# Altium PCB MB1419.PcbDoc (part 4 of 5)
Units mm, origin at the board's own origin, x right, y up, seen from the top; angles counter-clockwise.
Board outline 31 x 41 mm, 8 copper layers (Top Layer, Signal Layer 1, Signal Layer 2, Signal Layer 3, Signal Layer 4, Signal Layer 5, Signal Layer 6, Bottom Layer), stack 1.536 mm thick; 212 components, 125 nets, 637 pads, 2405 vias.
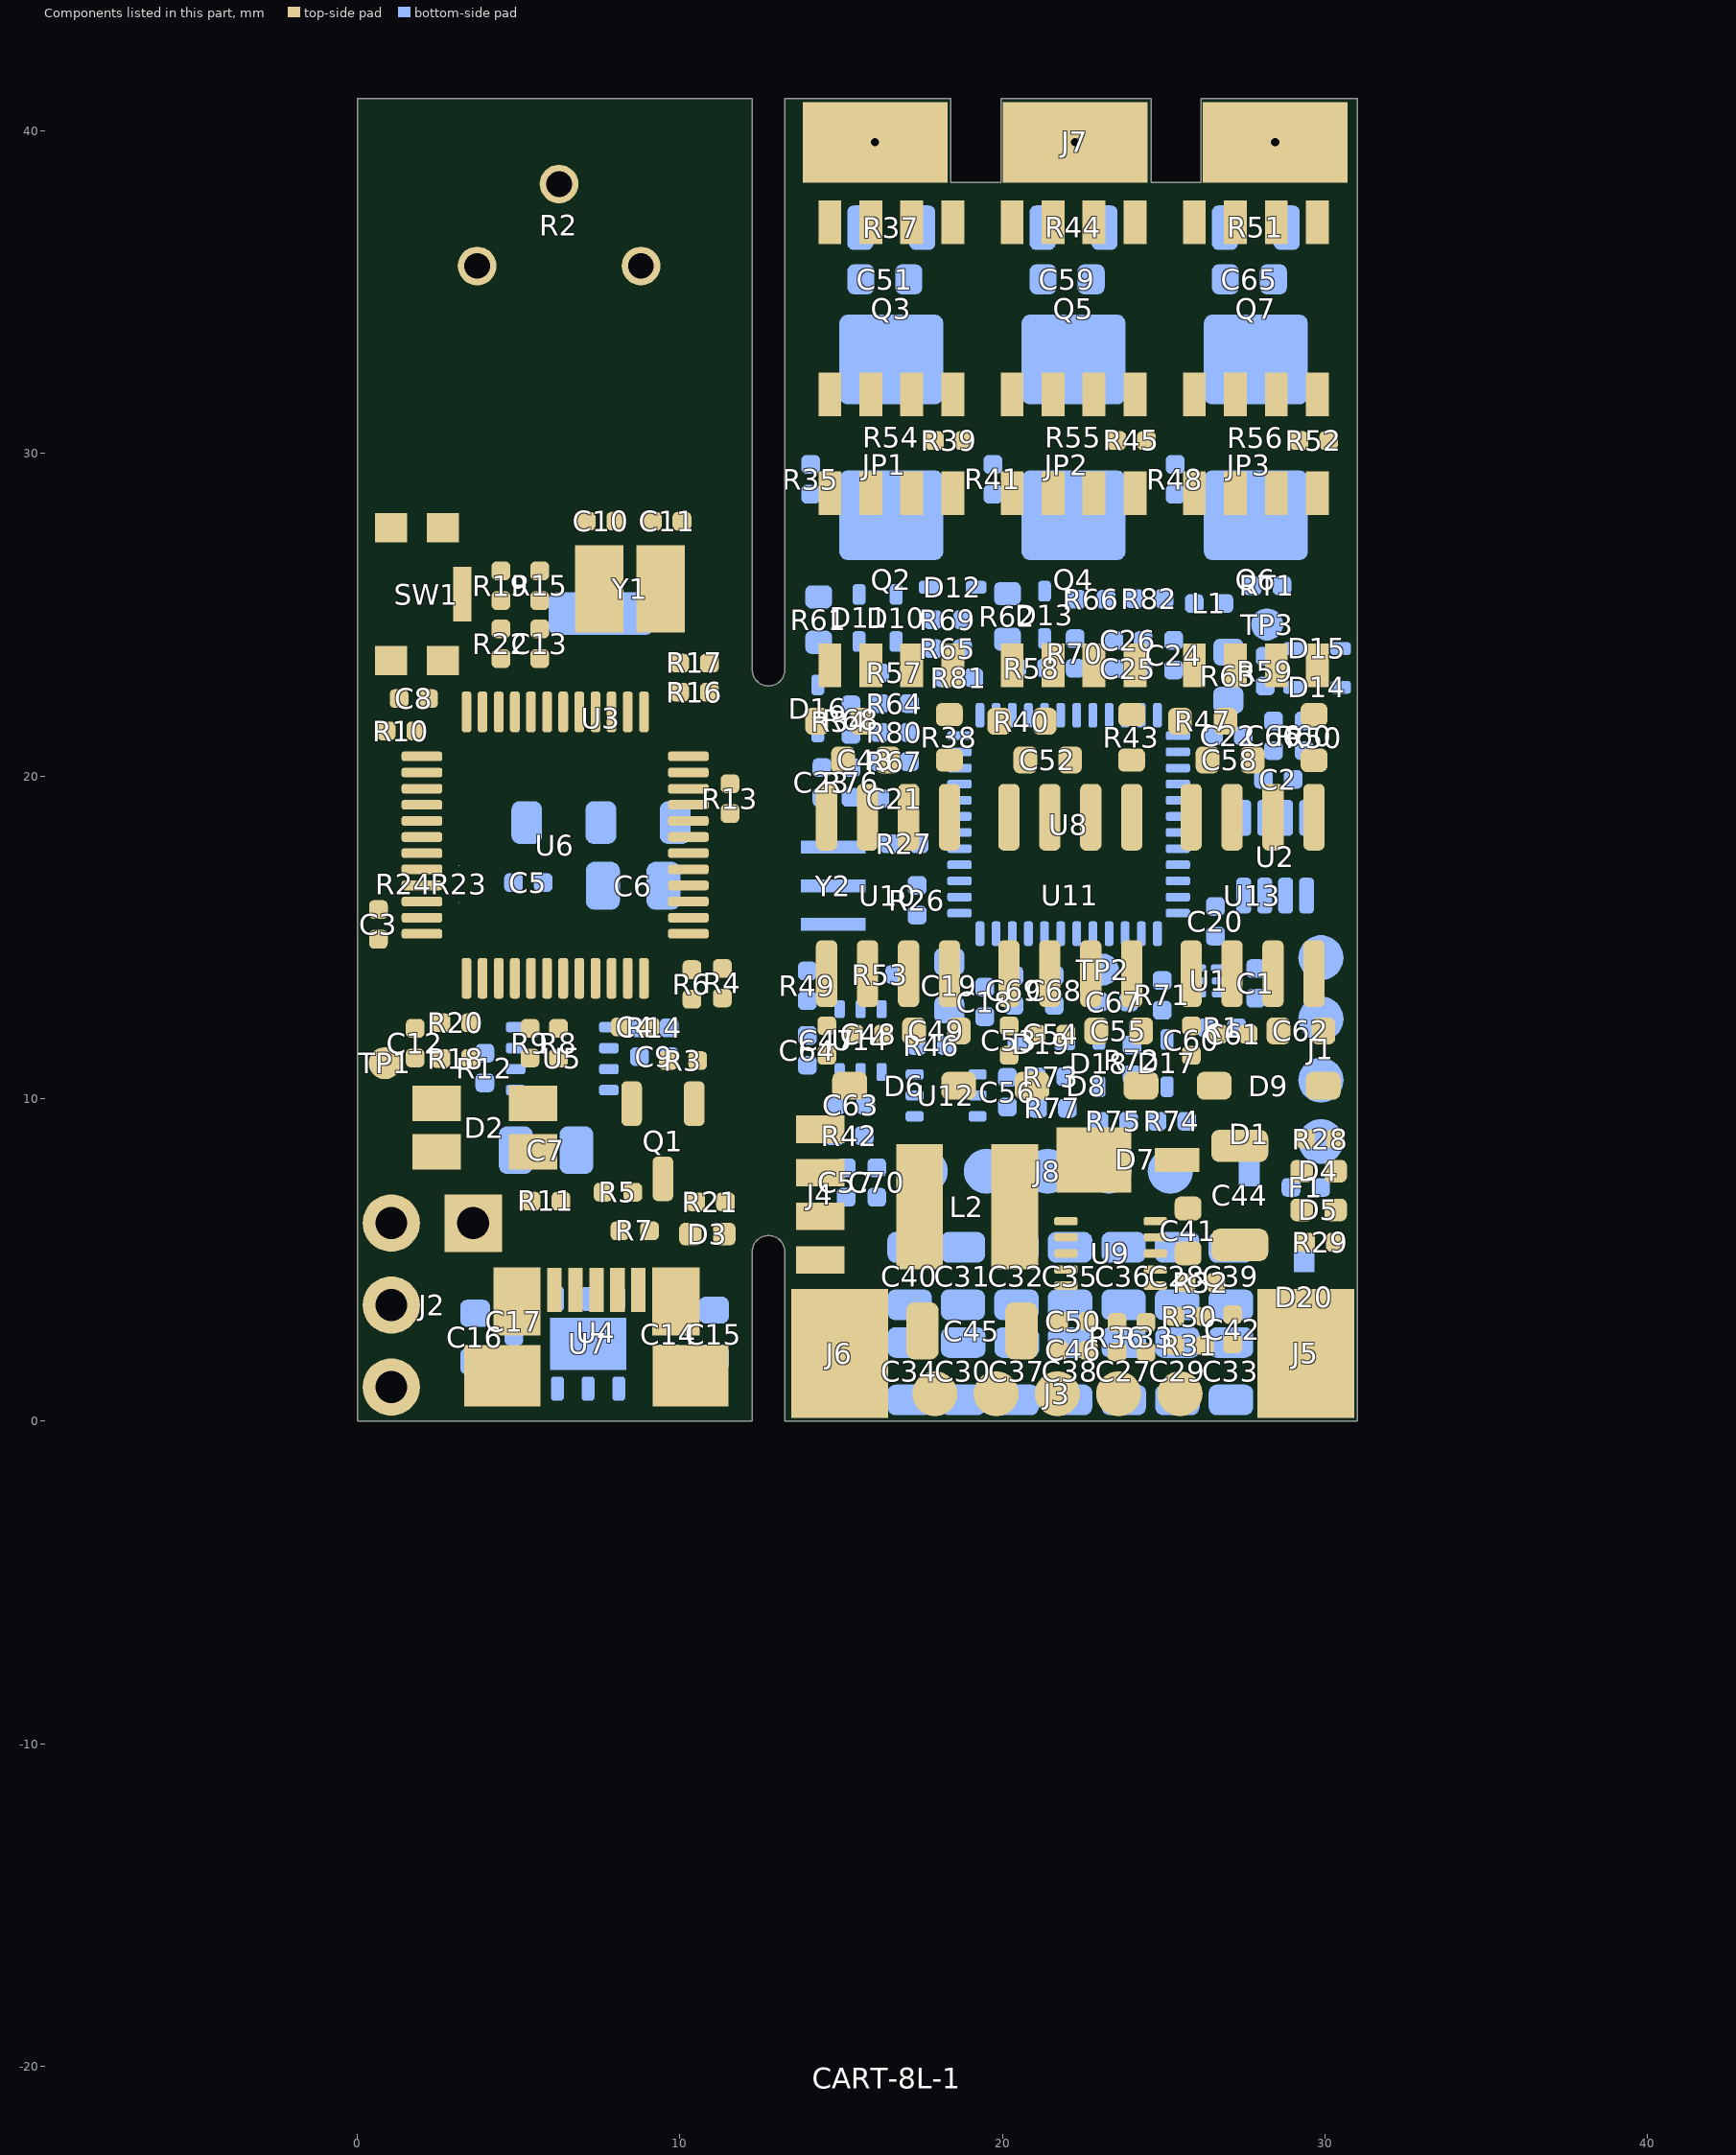
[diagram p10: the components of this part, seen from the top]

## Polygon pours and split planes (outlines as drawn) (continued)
V+ on Bottom Layer "V+_L08_P048" (solid, pour order 48): 27.65,2 16.65,2 16.65,4 27.65,4 30.75,4 30.85,3.9 30.85,0.1 28.05,0.1 28.05,1.6 27.65,2
"VSHUNT_2 +" on Bottom Layer "VSHUNT_2_+_L08_P050" (solid, pour order 50): 19.8,34.4 19.8,30.8 20.4,30.2 23.4,30.2 23.8,30.6 23.8,34.2 23.4,34.6 20,34.6 19.8,34.4
"VSHUNT_3 +" on Bottom Layer "VSHUNT_3_+_L08_P052" (solid, pour order 52): 25.45,34.4 25.45,30.8 26.05,30.2 29.05,30.2 29.45,30.6 29.45,34.2 29.05,34.6 25.65,34.6 25.45,34.4
"VSHUNT_1 +" on Bottom Layer "VSHUNT_1_+_L08_P054" (solid, pour order 54): 14.15,34.4 14.15,30.8 14.75,30.2 17.75,30.2 18.15,30.6 18.15,34.2 17.75,34.6 14.35,34.6 14.15,34.4
D on Bottom Layer "D_L08_P056" (solid, pour order 56): 42 vertices, not listed, extent 29.25,9.9 30.725,11.25
OUT3 on Bottom Layer "OUT3_L08_P058" (solid, pour order 58): 26.2,40.9 26.2,38 30.7,38 30.7,40.9 26.2,40.9
OUT1 on Bottom Layer "OUT1_L08_P060" (solid, pour order 60): 13.8,40.9 13.8,38 18.3,38 18.3,40.9 13.8,40.9
OUT2 on Bottom Layer "OUT2_L08_P062" (solid, pour order 62): 20,40.9 20,38 24.5,38 24.5,40.9 20,40.9
NetF1_1 on Bottom Layer "NETF1_1_L08_P064" (solid, pour order 64): 42 vertices, not listed, extent 29.225,7.95 30.725,9.35
+10V on Bottom Layer "+10V_L08_P066" (solid, pour order 66): 11.9,9.25 12.25,9.25 12.3,9.3 12.3,9.95 11.95,10.3 11.55,10.3 11.5,10.25 11.5,9.65 11.9,9.25
+10V on Bottom Layer "+10V_L08_P068" (solid, pour order 68): 13.25,9.3 14.15,9.3 14.2,9.35 14.2,10.45 14.15,10.5 13.75,10.5 13.25,10 13.25,9.3
+10V on Bottom Layer "+10V_L08_P070" (solid, pour order 70): 19,10.25 19,9.1 19.1,9 20.4,9 20.5,9.1 20.5,10 20.4,10.1 19.85,10.1 19.7,10.25 19,10.25
+5V on Bottom Layer "+5V_L08_P072" (solid, pour order 72): 11.5,9.05 12.25,9.05 12.3,9 12.3,8.45 12.25,8.4 11.55,8.4 11.45,8.5 11.45,9 11.5,9.05
+5V on Bottom Layer "+5V_L08_P074" (solid, pour order 74): 13.3,7.7 14.05,7.7 14.2,7.85 14.2,8.75 14,8.95 13.3,8.95 13.2,8.85 13.2,7.8 13.3,7.7
USART2_RX on Top Layer "USART2_RX_L01_P076" (solid, pour order 76): 42 vertices, not listed, extent 21,0.075 22.4,1.575
USART2_RX_ST_LINK on Top Layer "USART2_RX_ST_LINK_L01_P078" (solid, pour order 78): 42 vertices, not listed, extent 19.1,0.075 20.5,1.575
+3.3V on Top Layer "+3.3V_L01_P080" (solid, pour order 80): 13.4,6.75 13.4,5.95 15.55,5.95 15.55,6.75 13.4,6.75
GND on Top Layer "GND_L01_P082" (solid, pour order 82): 24.75,7.8 24.75,8.8 24.95,9 28.05,9 28.15,8.9 28.15,7.9 27.85,7.6 24.95,7.6 24.75,7.8
GND on Top Layer "GND_L01_P084" (solid, pour order 84): 42 vertices, not listed, extent 24.8,0.075 26.2,1.575
GND on Top Layer "GND_L01_P086" (solid, pour order 86): 21.1,3.55 21.1,2.1 21,2 19.85,2 19.75,2.1 19.75,3.5 19.85,3.6 21.05,3.6 21.1,3.55
GND on Top Layer "GND_L01_P088" (solid, pour order 88): 13.375,5.4 13.375,4.6 15.525,4.6 15.525,5.4 13.375,5.4
GND on Top Layer "GND_L01_P090" (solid, pour order 90): 13.35,5.3 13.35,0.1 16.45,0.1 16.45,4.2 15.25,5.4 13.45,5.4 13.35,5.3
NetD7_C on Top Layer "NETD7_C_L01_P092" (solid, pour order 92): 23.95,9.1 21.75,9.1 21.25,8.6 19.65,8.6 19.65,5.6 22.25,5.6 22.25,6.9 22.35,7 23.95,7 23.95,9.1
V+ on Top Layer "V+_L01_P094" (solid, pour order 94): 19 vertices, not listed, extent 24.45,0.1 30.85,7
V+ on Top Layer "V+_L01_P096" (solid, pour order 96): 19.3,27.3 19.3,22.7 25,22.7 25,27.3 19.3,27.3
V+ on Top Layer "V+_L01_P098" (solid, pour order 98): 24.95,27.3 24.95,22.7 30.65,22.7 30.65,27.3 24.95,27.3
V+ on Top Layer "V+_L01_P100" (solid, pour order 100): 13.65,27.3 13.65,22.7 19.35,22.7 19.35,27.3 13.65,27.3
"VSHUNT_2 +" on Top Layer "VSHUNT_2_+_L01_P102" (solid, pour order 102): 19.8,32.8 19.8,30.8 20.3,30.3 23.2,30.3 23.2,32.8 19.8,32.8
T_JTMS on Top Layer "T_JTMS_L01_P104" (solid, pour order 104): 13.4,9.45 13.4,8.65 15.55,8.65 15.55,9.45 13.4,9.45
T_JTCK on Top Layer "T_JTCK_L01_P106" (solid, pour order 106): 13.4,8.1 13.4,7.3 15.55,7.3 15.55,8.1 13.4,8.1
"VSHUNT_3 +" on Top Layer "VSHUNT_3_+_L01_P108" (solid, pour order 108): 25.45,32.8 25.45,30.8 25.95,30.3 28.85,30.3 28.85,32.8 25.45,32.8
"VSHUNT_1 +" on Top Layer "VSHUNT_1_+_L01_P110" (solid, pour order 110): 14.15,32.8 14.15,30.8 14.65,30.3 17.55,30.3 17.55,32.8 14.15,32.8
OUT3 on Top Layer "OUT3_L01_P112" (solid, pour order 112): 25.1,38.25 25.1,33.3 30.75,33.3 30.75,40.9 26.25,40.9 26.25,38.25 25.1,38.25
OUT3 on Top Layer "OUT3_L01_P114" (solid, pour order 114): 26.8,27.9 26.8,29.8 30.15,29.8 30.15,27.9 26.8,27.9
OUT1 on Top Layer "OUT1_L01_P116" (solid, pour order 116): 13.55,40.9 13.55,33.3 19.15,33.3 19.15,38.2 18.25,38.2 18.25,40.9 13.55,40.9
OUT1 on Top Layer "OUT1_L01_P118" (solid, pour order 118): 15.5,27.9 15.5,29.8 18.85,29.8 18.85,27.9 15.5,27.9
OUT2 on Top Layer "OUT2_L01_P120" (solid, pour order 120): 19.5,38.15 19.5,33.3 24.8,33.3 24.8,38.25 24.45,38.25 24.45,38.45 24.45,40.9 20.05,40.9 20.05,38.25 20.05,38.15 19.5,38.15
OUT2 on Top Layer "OUT2_L01_P122" (solid, pour order 122): 21.15,27.9 21.15,29.8 24.5,29.8 24.5,27.9 21.15,27.9
PWM on Top Layer "PWM_L01_P124" (solid, pour order 124): 42 vertices, not listed, extent 22.9,0.075 24.3,1.575
+10V on Top Layer "+10V_L01_P126" (solid, pour order 126): 30 vertices, not listed, extent 16.65,2 30.45,10.7
+5V on Top Layer "+5V_L01_P128" (solid, pour order 128): 42 vertices, not listed, extent 17.2,0.1 18.6,1.6
+3V3_ST_LINK on Signal Layer 5 "+3V3_ST_LINK_L06_P130" (solid, pour order 130): 988 vertices, not listed, extent 0.25,0.2 12.05,40.7
GND on Signal Layer 5 "GND_L06_P134" (solid, pour order 134): 25.7,29.5 30.75,29.5 30.75,26.5 13.45,26.5 13.45,28.1 14.4,28.1 14.4,29.5 18.95,29.5 18.95,28.1 20.05,28.1 20.05,29.5 24.6,29.5 24.6,28.1 25.7,28.1 25.7,29.5
GND on Signal Layer 5 "GND_L06_P136" (solid, pour order 136): 19.55,2.05 21.6,2.05 21.7,2.15 21.7,3.7 21.6,3.8 19.55,3.8 19.45,3.7 19.45,2.15 19.55,2.05
"VSHUNT_2 +" on Signal Layer 5 "VSHUNT_2_+_L06_P138" (solid, pour order 138): 20.4,30.2 23.95,30.2 24.15,30.4 24.15,32.55 24.3,32.7 24.75,32.7 25.05,33 25.05,37 24.85,37.2 20.05,37.2 19.8,36.95 19.8,30.8 20.4,30.2
"VSHUNT_3 +" on Signal Layer 5 "VSHUNT_3_+_L06_P140" (solid, pour order 140): 26.05,30.2 29.6,30.2 29.8,30.4 29.8,32.55 29.95,32.7 30.4,32.7 30.7,33 30.7,37 30.5,37.2 25.65,37.2 25.45,37 25.45,30.8 26.05,30.2
"VSHUNT_1 +" on Signal Layer 5 "VSHUNT_1_+_L06_P142" (solid, pour order 142): 14.75,30.2 18.3,30.2 18.5,30.4 18.5,32.55 18.65,32.7 19.05,32.7 19.35,33 19.35,37 19.15,37.2 14.35,37.2 14.15,37 14.15,30.8 14.75,30.2
+10V on Signal Layer 5 "+10V_L06_P144" (solid, pour order 144): 17.5,8.05 19.4,8.05 20.35,9 20.35,9.45 19.7,10.1 16.9,10.1 16.9,8.65 17.5,8.05
+3.3V on Signal Layer 5 "+3.3V_L06_P132" (solid, pour order 132): 738 vertices, not listed, extent 13.55,5 30.8,26
+3V3_ST_LINK on Signal Layer 1 "+3V3_ST_LINK_L02_P146" (solid, pour order 146): 1106 vertices, not listed, extent 0.25,0.2 12.05,40.7
OUT3 on Signal Layer 1 "OUT3_L02_P150" (solid, pour order 150): 205 vertices, not listed, extent 25.05,27.8 30.75,40.8
OUT1 on Signal Layer 1 "OUT1_L02_P152" (solid, pour order 152): 119 vertices, not listed, extent 13.75,27.8 19.05,40.8
OUT2 on Signal Layer 1 "OUT2_L02_P154" (solid, pour order 154): 150 vertices, not listed, extent 19.4,27.8 24.7,40.8
V+ on Signal Layer 1 "V+_L02_P148" (solid, pour order 148): 13.45,27.1 30.85,27.1 30.85,0.1 16.5,0.1 16.5,5.6 13.45,5.6 13.45,27.1
GND on Signal Layer 4 "GND_L05_P156" (solid, pour order 156): 599 vertices, not listed, extent 0.25,0.2 11.95,40.7
GND on Signal Layer 4 "GND_L05_P158" (solid, remove dead copper, pour order 158): 1190 vertices, not listed, extent 13.45,0.1 30.85,26
GND on Signal Layer 4 "GND_L05_P160" (solid, pour order 160): 15.7,26.35 18.3,26.35 18.5,26.55 18.5,29.1 18.3,29.3 15.7,29.3 15.5,29.1 15.5,26.55 15.7,26.35
GND on Signal Layer 4 "GND_L05_P162" (solid, pour order 162): 21.3,26.35 24,26.35 24.2,26.55 24.2,29.1 24,29.3 21.3,29.3 21.1,29.1 21.1,26.55 21.3,26.35
GND on Signal Layer 4 "GND_L05_P164" (solid, pour order 164): 27,26.35 29.6,26.35 29.8,26.55 29.8,29.1 29.6,29.3 27,29.3 26.8,29.1 26.8,26.55 27,26.35
"VSHUNT_2 +" on Signal Layer 4 "VSHUNT_2_+_L05_P166" (solid, pour order 166): 20.2,30.4 23.85,30.4 24.15,30.7 24.15,32.55 24.3,32.7 24.75,32.7 25.05,33 25.05,37 24.85,37.2 20.05,37.2 19.8,36.95 19.8,30.8 20.2,30.4
"VSHUNT_3 +" on Signal Layer 4 "VSHUNT_3_+_L05_P168" (solid, pour order 168): 25.85,30.4 29.65,30.4 29.8,30.55 29.8,32.55 29.95,32.7 30.4,32.7 30.7,33 30.7,37 30.5,37.2 25.65,37.2 25.45,37 25.45,30.8 25.85,30.4
"VSHUNT_1 +" on Signal Layer 4 "VSHUNT_1_+_L05_P170" (solid, pour order 170): 14.55,30.4 18.35,30.4 18.5,30.55 18.5,32.55 18.65,32.7 19.05,32.7 19.35,33 19.35,37 19.15,37.2 14.35,37.2 14.15,37 14.15,30.8 14.55,30.4
GND on Signal Layer 6 "GND_L07_P172" (solid, pour order 172): 615 vertices, not listed, extent 0.25,0.2 13.55,40.7
GND on Signal Layer 6 "GND_L07_P176" (solid, pour order 176): 25.7,28.1 25.7,29.5 30.75,29.5 30.75,26.5 13.45,26.5 13.45,28.1 14.4,28.1 14.4,29.5 18.95,29.5 18.95,28.1 20.05,28.1 20.05,29.5 24.6,29.5 24.6,28.1 25.7,28.1
"VSHUNT_2 +" on Signal Layer 6 "VSHUNT_2_+_L07_P184" (solid, pour order 184): 20.4,30.2 23.95,30.2 24.15,30.4 24.15,32.55 24.3,32.7 24.75,32.7 25.05,33 25.05,37 24.85,37.2 20.05,37.2 19.8,36.95 19.8,30.8 20.4,30.2
"VSHUNT_3 +" on Signal Layer 6 "VSHUNT_3_+_L07_P186" (solid, pour order 186): 26.05,30.2 29.6,30.2 29.8,30.4 29.8,32.55 29.95,32.7 30.4,32.7 30.7,33 30.7,37 30.5,37.2 25.65,37.2 25.45,37 25.45,30.8 26.05,30.2
"VSHUNT_1 +" on Signal Layer 6 "VSHUNT_1_+_L07_P188" (solid, pour order 188): 14.75,30.2 18.3,30.2 18.5,30.4 18.5,32.55 18.65,32.7 19.05,32.7 19.35,33 19.35,37 19.15,37.2 14.35,37.2 14.15,37 14.15,30.8 14.75,30.2
GND on Signal Layer 6 "GND_L07_P174" (solid, pour order 174): 1099 vertices, not listed, extent 13.45,0.1 30.85,26
GND on Signal Layer 3 "GND_L04_P192" (solid, pour order 192): 1421 vertices, not listed, extent 0.25,0.2 11.95,40.7
GND on Signal Layer 3 "GND_L04_P194" (solid, pour order 194): 1244 vertices, not listed, extent 13.45,0.1 30.85,16.6
GND on Signal Layer 3 "GND_L04_P196" (solid, pour order 196): 15.65,26.35 18.15,26.35 18.35,26.55 18.35,29.15 18.15,29.35 15.65,29.35 15.45,29.15 15.45,26.55 15.65,26.35
GND on Signal Layer 3 "GND_L04_P198" (solid, pour order 198): 21.3,26.35 23.8,26.35 23.95,26.5 23.95,29.2 23.8,29.35 21.3,29.35 21.1,29.15 21.1,26.55 21.3,26.35
GND on Signal Layer 3 "GND_L04_P200" (solid, pour order 200): 27,26.35 29.5,26.35 29.7,26.55 29.7,29.15 29.5,29.35 27,29.35 26.8,29.15 26.8,26.55 27,26.35
GND on Signal Layer 3 "GND_L04_P202" (solid, pour order 202): 149 vertices, not listed, extent 0.25,4.372 2,5.269
GND on Signal Layer 3 "GND_L04_P204" (solid, pour order 204): 120 vertices, not listed, extent 0.25,2.044 2,2.828
"VSHUNT_2 +" on Signal Layer 3 "VSHUNT_2_+_L04_P206" (solid, pour order 206): 20.4,30.2 23.7,30.2 23.9,30.4 23.9,32.55 24.05,32.7 24.75,32.7 25.05,33 25.05,37 24.85,37.2 20.05,37.2 19.8,36.95 19.8,30.8 20.4,30.2
"VSHUNT_3 +" on Signal Layer 3 "VSHUNT_3_+_L04_P208" (solid, pour order 208): 26.05,30.2 29.4,30.2 29.6,30.4 29.6,32.55 29.75,32.7 30.4,32.7 30.7,33 30.7,37 30.5,37.2 25.65,37.2 25.45,37 25.45,30.8 26.05,30.2
"VSHUNT_1 +" on Signal Layer 3 "VSHUNT_1_+_L04_P210" (solid, pour order 210): 14.75,30.2 18.05,30.2 18.25,30.4 18.25,32.55 18.4,32.7 19.05,32.7 19.35,33 19.35,37 19.15,37.2 14.35,37.2 14.15,37 14.15,30.8 14.75,30.2
+10V on Signal Layer 3 "+10V_L04_P190" (solid, pour order 190): 17.75,9.35 18.9,9.35 19.05,9.2 19.05,8.15 18.6,7.7 18.6,2.95 18.45,2.8 17.25,2.8 17.1,2.95 17.1,8.7 17.75,9.35
GND on Signal Layer 2 "GND_L03_P214" (solid, pour order 214): 611 vertices, not listed, extent 0.25,0.2 12.05,40.7
OUT3 on Signal Layer 2 "OUT3_L03_P220" (solid, pour order 220): 125 vertices, not listed, extent 25.05,29.6 30.75,40.9
OUT1 on Signal Layer 2 "OUT1_L03_P222" (solid, pour order 222): 43 vertices, not listed, extent 13.5,29.6 19.15,40.9
OUT2 on Signal Layer 2 "OUT2_L03_P224" (solid, pour order 224): 69 vertices, not listed, extent 19.45,29.6 24.7,40.9
+10V on Signal Layer 2 "+10V_L03_P212" (solid, pour order 212): 17.25,2.25 18.45,2.25 18.6,2.4 18.6,4.1 18.5,4.2 17.4,4.2 17.1,3.9 17.1,2.4 17.25,2.25
GND on Signal Layer 2 "GND_L03_P216" (solid, pour order 216): 222 vertices, not listed, extent 13.45,0.1 30.8,29.35
GND on Signal Layer 2 "GND_L03_P218" (solid, pour order 218): 19.7,2.15 21.35,2.15 21.45,2.25 21.45,3.4 21.35,3.5 19.7,3.5 19.6,3.4 19.6,2.25 19.7,2.15
no net on Bottom Overlay (solid): 449 vertices, not listed, extent 7.23,5.857 11.498,8.504
no net on Bottom Overlay (solid): 569 vertices, not listed, extent 6.812,4.5 11.069,7.131
no net on Bottom Overlay (solid): 281 vertices, not listed, extent 8.287,5.646 9.263,7.364
no net on Bottom Overlay (solid): 79 vertices, not listed, extent 9.425,5.67 10.13,7.337
no net on Bottom Overlay (solid): 2340 vertices, not listed, extent 3.273,26.067 11.849,34.646
no net on Bottom Overlay (solid): 86 vertices, not listed, extent 9.29,34.903 11.985,39.849
no net on Bottom Overlay (solid): 7.292,37.052 5.743,37.052 5.743,37.801 7.292,37.801 7.292,37.052
no net on Bottom Overlay (solid): 86 vertices, not listed, extent 5.243,34.954 7.939,39.899
no net on Top Overlay (solid): 225 vertices, not listed, extent 3.826,27.949 5.645,29.65
no net on Top Overlay (solid): 256 vertices, not listed, extent 2.412,28.411 7.181,30.488
no net on Top Overlay (solid): 192 vertices, not listed, extent 5.462,27.949 6.836,29.65
no net on Drill Drawing (solid): -80.125,51.535 -80.125,50.621 -79.49,50.621 -79.49,2.462 -80.125,2.462 -80.125,1.548 -76.315,1.548 -76.315,2.462 -76.95,2.462 -76.95,50.621 -76.315,50.621 -76.315,51.535 -80.125,51.535
no net on Drill Drawing (solid): -75.045,51.535 -74.41,43.61 -71.87,43.61 -71.235,51.535 -75.045,51.535
no net on Drill Drawing (solid): -69.965,44.525 -69.33,36.6 -66.79,36.6 -66.155,44.525 -69.965,44.525
no net on Drill Drawing (solid): -64.885,37.514 -64.885,36.6 -64.25,36.6 -64.25,16.483 -64.885,16.483 -64.885,15.569 -61.075,15.569 -61.075,16.483 -61.71,16.483 -61.71,36.6 -61.075,36.6 -61.075,37.514 -64.885,37.514
no net on Drill Drawing (solid): -59.805,8.558 -55.995,8.558 -56.63,16.483 -59.17,16.483 -59.805,8.558
no net on Drill Drawing (solid): -54.725,1.548 -50.915,1.548 -51.55,9.473 -54.09,9.473 -54.725,1.548
no net on Drill Drawing (solid): -49.645,51.535 -49.01,43.61 -46.47,43.61 -45.835,51.535 -49.645,51.535
no net on Drill Drawing (solid): -49.645,44.525 -49.01,36.6 -46.47,36.6 -45.835,44.525 -49.645,44.525
no net on Drill Drawing (solid): -44.565,8.558 -40.755,8.558 -41.39,16.483 -43.93,16.483 -44.565,8.558
no net on Drill Drawing (solid): -44.565,1.548 -40.755,1.548 -41.39,9.473 -43.93,9.473 -44.565,1.548

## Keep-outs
Signal Layer 2:
  region: 25.9,8.9 26.95,8.9 27.25,8.6 27.25,7.85 26.85,7.45 26.2,7.45 25.8,7.85 25.8,8.8
  region: 22.65,6.2 24.05,6.2 24.25,6 24.25,4.45 24,4.2 22.7,4.2 22.4,4.5 22.4,5.95
  lines w0.127: 19.525,2.225 19.525,3.42 19.67,3.565 21.38,3.565 21.525,3.42 21.525,2.225 21.38,2.08 19.67,2.08 19.525,2.225

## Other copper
Top Layer:
  drawing of 204 lines, arcs and shapes, not listed
  text "1" at 0.575,38 h1.3 r270
Signal Layer 1:
  pour cut-out: 11.839,27.9 11.802,28.087 11.696,28.246 11.537,28.352 11.35,28.389 11.163,28.352 11.004,28.246 10.898,28.087 10.861,27.9 10.898,27.713 11.004,27.554 11.163,27.448 11.35,27.411 11.537,27.448 11.696,27.554 11.802,27.713 11.839,27.9
  pour cut-out: 11.839,24.75 11.802,24.937 11.696,25.096 11.537,25.202 11.35,25.239 11.163,25.202 11.004,25.096 10.898,24.937 10.861,24.75 10.898,24.563 11.004,24.404 11.163,24.298 11.35,24.261 11.537,24.298 11.696,24.404 11.802,24.563 11.839,24.75
  pour cut-out: 11.226,22.1 11.202,22.221 11.134,22.324 11.031,22.392 10.91,22.416 10.789,22.392 10.686,22.324 10.618,22.221 10.594,22.1 10.618,21.979 10.686,21.876 10.789,21.808 10.91,21.784 11.031,21.808 11.134,21.876 11.202,21.979 11.226,22.1
  pour cut-out: 11.866,20.35 11.842,20.471 11.774,20.574 11.671,20.642 11.55,20.666 11.429,20.642 11.326,20.574 11.258,20.471 11.234,20.35 11.258,20.229 11.326,20.126 11.429,20.058 11.55,20.034 11.671,20.058 11.774,20.126 11.842,20.229 11.866,20.35
  pour cut-out: 10.989,6.65 10.952,6.837 10.846,6.996 10.687,7.102 10.5,7.139 10.313,7.102 10.154,6.996 10.048,6.837 10.011,6.65 10.048,6.463 10.154,6.304 10.313,6.198 10.5,6.161 10.687,6.198 10.846,6.304 10.952,6.463 10.989,6.65
  pour cut-out: 9.539,20.55 9.502,20.737 9.396,20.896 9.237,21.002 9.05,21.039 8.863,21.002 8.704,20.896 8.598,20.737 8.561,20.55 8.598,20.363 8.704,20.204 8.863,20.098 9.05,20.061 9.237,20.098 9.396,20.204 9.502,20.363 9.539,20.55
  pour cut-out: 8.466,11.7 8.442,11.821 8.374,11.924 8.271,11.992 8.15,12.016 8.029,11.992 7.926,11.924 7.858,11.821 7.834,11.7 7.858,11.579 7.926,11.476 8.029,11.408 8.15,11.384 8.271,11.408 8.374,11.476 8.442,11.579 8.466,11.7
  pour cut-out: 8.196,12.88 8.172,13.001 8.104,13.104 8.001,13.172 7.88,13.196 7.759,13.172 7.656,13.104 7.588,13.001 7.564,12.88 7.588,12.759 7.656,12.656 7.759,12.588 7.88,12.564 8.001,12.588 8.104,12.656 8.172,12.759 8.196,12.88
  pour cut-out: 7.516,15.11 7.492,15.231 7.424,15.334 7.321,15.402 7.2,15.426 7.079,15.402 6.976,15.334 6.908,15.231 6.884,15.11 6.908,14.989 6.976,14.886 7.079,14.818 7.2,14.794 7.321,14.818 7.424,14.886 7.492,14.989 7.516,15.11
  pour cut-out: 7.158,38.355 7.127,38.59 7.036,38.809 6.892,38.997 6.704,39.141 6.485,39.232 6.25,39.263 6.015,39.232 5.796,39.141 5.608,38.997 5.464,38.809 5.373,38.59 5.342,38.355 5.373,38.12 5.464,37.901 5.608,37.713 5.796,37.569 6.015,37.478 6.25,37.447 6.485,37.478 6.704,37.569 6.892,37.713 7.036,37.901 7.127,38.12 7.158,38.355
  pour cut-out: 5.696,22.88 5.672,23.001 5.604,23.104 5.501,23.172 5.38,23.196 5.259,23.172 5.156,23.104 5.088,23.001 5.064,22.88 5.088,22.759 5.156,22.656 5.259,22.588 5.38,22.564 5.501,22.588 5.604,22.656 5.672,22.759 5.696,22.88
  pour cut-out: 6.489,17.45 6.452,17.637 6.346,17.796 6.187,17.902 6,17.939 5.813,17.902 5.654,17.796 5.548,17.637 5.511,17.45 5.548,17.263 5.654,17.104 5.813,16.998 6,16.961 6.187,16.998 6.346,17.104 6.452,17.263 6.489,17.45
  pour cut-out: 5.356,24.56 5.332,24.681 5.264,24.784 5.161,24.852 5.04,24.876 4.919,24.852 4.816,24.784 4.748,24.681 4.724,24.56 4.748,24.439 4.816,24.336 4.919,24.268 5.04,24.244 5.161,24.268 5.264,24.336 5.332,24.439 5.356,24.56
  pour cut-out: 4.689,11.8 4.652,11.987 4.546,12.146 4.387,12.252 4.2,12.289 4.013,12.252 3.854,12.146 3.748,11.987 3.711,11.8 3.748,11.613 3.854,11.454 4.013,11.348 4.2,11.311 4.387,11.348 4.546,11.454 4.652,11.613 4.689,11.8
  pour cut-out: 4.618,35.815 4.587,36.05 4.496,36.269 4.352,36.457 4.164,36.601 3.945,36.692 3.71,36.723 3.475,36.692 3.256,36.601 3.068,36.457 2.924,36.269 2.833,36.05 2.802,35.815 2.833,35.58 2.924,35.361 3.068,35.173 3.256,35.029 3.475,34.938 3.71,34.907 3.945,34.938 4.164,35.029 4.352,35.173 4.496,35.361 4.587,35.58 4.618,35.815
  pour cut-out: 3.739,20.3 3.702,20.487 3.596,20.646 3.437,20.752 3.25,20.789 3.063,20.752 2.904,20.646 2.798,20.487 2.761,20.3 2.798,20.113 2.904,19.954 3.063,19.848 3.25,19.811 3.437,19.848 3.596,19.954 3.702,20.113 3.739,20.3
  pour cut-out: 3.016,22.4 2.992,22.521 2.924,22.624 2.821,22.692 2.7,22.716 2.579,22.692 2.476,22.624 2.408,22.521 2.384,22.4 2.408,22.279 2.476,22.176 2.579,22.108 2.7,22.084 2.821,22.108 2.924,22.176 2.992,22.279 3.016,22.4
  pour cut-out: 3.439,1.1 3.402,1.287 3.296,1.446 3.137,1.552 2.95,1.589 2.763,1.552 2.604,1.446 2.498,1.287 2.461,1.1 2.498,0.913 2.604,0.754 2.763,0.648 2.95,0.611 3.137,0.648 3.296,0.754 3.402,0.913 3.439,1.1
  pour cut-out: 2.116,12.65 2.092,12.771 2.024,12.874 1.921,12.942 1.8,12.966 1.679,12.942 1.576,12.874 1.508,12.771 1.484,12.65 1.508,12.529 1.576,12.426 1.679,12.358 1.8,12.334 1.921,12.358 2.024,12.426 2.092,12.529 2.116,12.65
  pour cut-out: 1.166,22.4 1.142,22.521 1.074,22.624 0.971,22.692 0.85,22.716 0.729,22.692 0.626,22.624 0.558,22.521 0.534,22.4 0.558,22.279 0.626,22.176 0.729,22.108 0.85,22.084 0.971,22.108 1.074,22.176 1.142,22.279 1.166,22.4
  pour cut-out: 1.739,9.85 1.702,10.037 1.596,10.196 1.437,10.302 1.25,10.339 1.063,10.302 0.904,10.196 0.798,10.037 0.761,9.85 0.798,9.663 0.904,9.504 1.063,9.398 1.25,9.361 1.437,9.398 1.596,9.504 1.702,9.663 1.739,9.85
  pour cut-out: 1.339,20.6 1.302,20.787 1.196,20.946 1.037,21.052 0.85,21.089 0.663,21.052 0.504,20.946 0.398,20.787 0.361,20.6 0.398,20.413 0.504,20.254 0.663,20.148 0.85,20.111 1.037,20.148 1.196,20.254 1.302,20.413 1.339,20.6
  pour cut-out: 1.339,12.9 1.302,13.087 1.196,13.246 1.037,13.352 0.85,13.389 0.663,13.352 0.504,13.246 0.398,13.087 0.361,12.9 0.398,12.713 0.504,12.554 0.663,12.448 0.85,12.411 1.037,12.448 1.196,12.554 1.302,12.713 1.339,12.9
  pour cut-out: 1.939,14.3 1.902,14.487 1.796,14.646 1.637,14.752 1.45,14.789 1.263,14.752 1.104,14.646 0.998,14.487 0.961,14.3 0.998,14.113 1.104,13.954 1.263,13.848 1.45,13.811 1.637,13.848 1.796,13.954 1.902,14.113 1.939,14.3
  pour cut-out: 3.089,14.501 3.052,14.688 2.946,14.846 2.787,14.952 2.6,14.99 2.413,14.952 2.254,14.846 2.148,14.688 2.111,14.501 2.148,14.313 2.254,14.155 2.413,14.049 2.6,14.012 2.787,14.049 2.946,14.155 3.052,14.313 3.089,14.501
  pour cut-out: 29.33,11.205 29.293,11.393 29.187,11.551 29.028,11.657 28.841,11.694 28.654,11.657 28.495,11.551 28.389,11.393 28.352,11.205 28.389,11.018 28.495,10.86 28.654,10.754 28.841,10.717 29.028,10.754 29.187,10.86 29.293,11.018 29.33,11.205
  pour cut-out: 29.216,8.75 29.192,8.871 29.124,8.974 29.021,9.042 28.9,9.066 28.779,9.042 28.676,8.974 28.608,8.871 28.584,8.75 28.608,8.629 28.676,8.526 28.779,8.458 28.9,8.434 29.021,8.458 29.124,8.526 29.192,8.629 29.216,8.75
  pour cut-out: 29.166,5.55 29.142,5.671 29.074,5.774 28.971,5.842 28.85,5.866 28.729,5.842 28.626,5.774 28.558,5.671 28.534,5.55 28.558,5.429 28.626,5.326 28.729,5.258 28.85,5.234 28.971,5.258 29.074,5.326 29.142,5.429 29.166,5.55
  pour cut-out: 27.926,12 27.902,12.121 27.834,12.224 27.731,12.292 27.61,12.316 27.489,12.292 27.386,12.224 27.318,12.121 27.294,12 27.318,11.879 27.386,11.776 27.489,11.708 27.61,11.684 27.731,11.708 27.834,11.776 27.902,11.879 27.926,12
  pour cut-out: 26.466,12.55 26.442,12.671 26.374,12.774 26.271,12.842 26.15,12.866 26.029,12.842 25.926,12.774 25.858,12.671 25.834,12.55 25.858,12.429 25.926,12.326 26.029,12.258 26.15,12.234 26.271,12.258 26.374,12.326 26.442,12.429 26.466,12.55
  pour cut-out: 27.039,11.3 27.002,11.487 26.896,11.646 26.737,11.752 26.55,11.789 26.363,11.752 26.204,11.646 26.098,11.487 26.061,11.3 26.098,11.113 26.204,10.954 26.363,10.848 26.55,10.811 26.737,10.848 26.896,10.954 27.002,11.113 27.039,11.3
  pour cut-out: 24.611,12.1 24.587,12.221 24.519,12.324 24.416,12.392 24.295,12.416 24.174,12.392 24.071,12.324 24.003,12.221 23.979,12.1 24.003,11.979 24.071,11.876 24.174,11.808 24.295,11.784 24.416,11.808 24.519,11.876 24.587,11.979 24.611,12.1
  pour cut-out: 24.666,1.5 24.642,1.621 24.574,1.724 24.471,1.792 24.35,1.816 24.229,1.792 24.126,1.724 24.058,1.621 24.034,1.5 24.058,1.379 24.126,1.276 24.229,1.208 24.35,1.184 24.471,1.208 24.574,1.276 24.642,1.379 24.666,1.5
  pour cut-out: 22.276,12 22.252,12.121 22.184,12.224 22.081,12.292 21.96,12.316 21.839,12.292 21.736,12.224 21.668,12.121 21.644,12 21.668,11.879 21.736,11.776 21.839,11.708 21.96,11.684 22.081,11.708 22.184,11.776 22.252,11.879 22.276,12
  pour cut-out: 21.766,1.087 21.742,1.208 21.674,1.311 21.571,1.379 21.45,1.403 21.329,1.379 21.226,1.311 21.158,1.208 21.134,1.087 21.158,0.966 21.226,0.863 21.329,0.795 21.45,0.771 21.571,0.795 21.674,0.863 21.742,0.966 21.766,1.087
  pour cut-out: 20.866,12.6 20.842,12.721 20.774,12.824 20.671,12.892 20.55,12.916 20.429,12.892 20.326,12.824 20.258,12.721 20.234,12.6 20.258,12.479 20.326,12.376 20.429,12.308 20.55,12.284 20.671,12.308 20.774,12.376 20.842,12.479 20.866,12.6
  pour cut-out: 20.466,11.35 20.442,11.471 20.374,11.574 20.271,11.642 20.15,11.666 20.029,11.642 19.926,11.574 19.858,11.471 19.834,11.35 19.858,11.229 19.926,11.126 20.029,11.058 20.15,11.034 20.271,11.058 20.374,11.126 20.442,11.229 20.466,11.35
  pour cut-out: 20.616,1.25 20.592,1.371 20.524,1.474 20.421,1.542 20.3,1.566 20.179,1.542 20.076,1.474 20.008,1.371 19.984,1.25 20.008,1.129 20.076,1.026 20.179,0.958 20.3,0.934 20.421,0.958 20.524,1.026 20.592,1.129 20.616,1.25
  pour cut-out: 19.239,11.6 19.202,11.787 19.096,11.946 18.937,12.052 18.75,12.089 18.563,12.052 18.404,11.946 18.298,11.787 18.261,11.6 18.298,11.413 18.404,11.254 18.563,11.148 18.75,11.111 18.937,11.148 19.096,11.254 19.202,11.413 19.239,11.6
  pour cut-out: 16.626,11.8 16.602,11.921 16.534,12.024 16.431,12.092 16.31,12.116 16.189,12.092 16.086,12.024 16.018,11.921 15.994,11.8 16.018,11.679 16.086,11.576 16.189,11.508 16.31,11.484 16.431,11.508 16.534,11.576 16.602,11.679 16.626,11.8
  pour cut-out: 15.466,7.45 15.442,7.571 15.374,7.674 15.271,7.742 15.15,7.766 15.029,7.742 14.926,7.674 14.858,7.571 14.834,7.45 14.858,7.329 14.926,7.226 15.029,7.158 15.15,7.134 15.271,7.158 15.374,7.226 15.442,7.329 15.466,7.45
  text "2" at 0.575,37.375 h1.3 r270
Signal Layer 2:
  pour cut-out: 23.633,11.626 cw(c24.09,11.626) 23.661,11.784 ccw(c23.566,11.819) 23.563,11.921 24.028,12.442 ccw(c24.129,12.452) 24.172,12.36 cw(c24.295,12.1) 24.295,12.387 cw(c24.295,12.1) 24.582,12.1 cw(c24.295,12.1) 24.522,11.924 24.522,11.772 24.525,11.765 cw(c24.09,11.626) 24.546,11.626 cw(c24.09,11.626)
  pour cut-out: 19.855,11.512 ccw(c19.855,11.055) 20.312,11.055 ccw(c19.855,11.055) 20.308,11.112 ccw(c20.155,11.355) 20.442,11.355 ccw(c20.155,11.355) 19.912,11.508 ccw(c19.855,11.055)
  pour cut-out: 14.833,12 ccw(c15.29,12) 15.29,11.543 ccw(c15.29,12) 15.747,12 ccw(c15.29,12) 15.29,12.457 ccw(c15.29,12)
  pour cut-out: 18.023,16.65 18.023,16.829 cw(c18.2,17.25) 17.743,17.25 cw(c18.2,17.25) 18.2,17.707 cw(c18.2,17.25) 18.656,17.275 18.657,17.256 18.677,17.235 18.677,16.65 cw(c18.35,16.65)
  pour cut-out: 23.673,16.65 ccw(c24,16.65) 24.327,16.65 24.327,17.131 ccw(c24,17.45) 24.457,17.45 ccw(c24,17.45) 23.543,17.45 ccw(c24,17.45) 23.673,17.131
  pour cut-out: 29.323,16.65 ccw(c29.65,16.65) 29.977,16.65 29.977,17.131 ccw(c29.65,17.45) 30.107,17.45 ccw(c29.65,17.45) 29.193,17.45 ccw(c29.65,17.45) 29.323,17.131
  pour cut-out: 28.384,11.205 ccw(c28.841,11.205) 28.841,10.749 ccw(c28.841,11.205) 29.298,11.205 ccw(c28.841,11.205) 28.841,11.662 ccw(c28.841,11.205)
  pour cut-out: 28.546,18.539 28.509,18.726 28.403,18.884 28.244,18.99 28.057,19.028 27.87,18.99 27.711,18.884 27.605,18.726 27.568,18.539 27.605,18.351 27.711,18.193 27.87,18.087 28.057,18.05 28.244,18.087 28.403,18.193 28.509,18.351 28.546,18.539
  pour cut-out: 27.939,17.3 27.902,17.487 27.796,17.646 27.637,17.752 27.45,17.789 27.263,17.752 27.104,17.646 26.998,17.487 26.961,17.3 26.998,17.113 27.104,16.954 27.263,16.848 27.45,16.811 27.637,16.848 27.796,16.954 27.902,17.113 27.939,17.3
  pour cut-out: 26.939,24.05 26.902,24.237 26.796,24.396 26.637,24.502 26.45,24.539 26.263,24.502 26.104,24.396 25.998,24.237 25.961,24.05 25.998,23.863 26.104,23.704 26.263,23.598 26.45,23.561 26.637,23.598 26.796,23.704 26.902,23.863 26.939,24.05
  pour cut-out: 27.016,11.3 26.98,11.478 26.879,11.629 26.728,11.73 26.55,11.766 26.372,11.73 26.221,11.629 26.12,11.478 26.084,11.3 26.12,11.122 26.221,10.971 26.372,10.87 26.55,10.834 26.728,10.87 26.879,10.971 26.98,11.122 27.016,11.3
  pour cut-out: 26.718,17.884 26.681,18.071 26.575,18.229 26.417,18.335 26.229,18.373 26.042,18.335 25.884,18.229 25.778,18.071 25.74,17.884 25.778,17.696 25.884,17.538 26.042,17.432 26.229,17.395 26.417,17.432 26.575,17.538 26.681,17.696 26.718,17.884
  pour cut-out: 26.589,16.75 26.552,16.937 26.446,17.096 26.287,17.202 26.1,17.239 25.913,17.202 25.754,17.096 25.648,16.937 25.611,16.75 25.648,16.563 25.754,16.404 25.913,16.298 26.1,16.261 26.287,16.298 26.446,16.404 26.552,16.563 26.589,16.75
  pour cut-out: 25.673,28.765 25.635,28.952 25.529,29.111 25.371,29.217 25.184,29.254 24.996,29.217 24.838,29.111 24.732,28.952 24.695,28.765 24.732,28.578 24.838,28.419 24.996,28.313 25.184,28.276 25.371,28.313 25.529,28.419 25.635,28.578 25.673,28.765
  pour cut-out: 23.379,24.51 23.342,24.697 23.236,24.856 23.077,24.962 22.89,24.999 22.703,24.962 22.544,24.856 22.438,24.697 22.401,24.51 22.438,24.323 22.544,24.164 22.703,24.058 22.89,24.021 23.077,24.058 23.236,24.164 23.342,24.323 23.379,24.51
  pour cut-out: 23.889,13.5 23.852,13.687 23.746,13.846 23.587,13.952 23.4,13.989 23.213,13.952 23.054,13.846 22.948,13.687 22.911,13.5 22.948,13.313 23.054,13.154 23.213,13.048 23.4,13.011 23.587,13.048 23.746,13.154 23.852,13.313 23.889,13.5
  pour cut-out: 23.189,22.8 23.152,22.987 23.046,23.146 22.887,23.252 22.7,23.289 22.513,23.252 22.354,23.146 22.248,22.987 22.211,22.8 22.248,22.613 22.354,22.454 22.513,22.348 22.7,22.311 22.887,22.348 23.046,22.454 23.152,22.613 23.189,22.8
  pour cut-out: 22.289,25 22.252,25.187 22.146,25.346 21.987,25.452 21.8,25.489 21.613,25.452 21.454,25.346 21.348,25.187 21.311,25 21.348,24.813 21.454,24.654 21.613,24.548 21.8,24.511 21.987,24.548 22.146,24.654 22.252,24.813 22.289,25
  pour cut-out: 22.468,14.1 22.431,14.287 22.325,14.446 22.167,14.552 21.979,14.589 21.792,14.552 21.634,14.446 21.528,14.287 21.49,14.1 21.528,13.913 21.634,13.754 21.792,13.648 21.979,13.611 22.167,13.648 22.325,13.754 22.431,13.913 22.468,14.1
  pour cut-out: 20.834,25.055 20.797,25.242 20.691,25.401 20.532,25.507 20.345,25.544 20.158,25.507 19.999,25.401 19.893,25.242 19.856,25.055 19.893,24.868 19.999,24.709 20.158,24.603 20.345,24.566 20.532,24.603 20.691,24.709 20.797,24.868 20.834,25.055
  pour cut-out: 20.023,28.765 19.985,28.952 19.879,29.111 19.721,29.217 19.534,29.254 19.346,29.217 19.188,29.111 19.082,28.952 19.045,28.765 19.082,28.578 19.188,28.419 19.346,28.313 19.534,28.276 19.721,28.313 19.879,28.419 19.985,28.578 20.023,28.765
  pour cut-out: 20.289,14.3 20.252,14.487 20.146,14.646 19.987,14.752 19.8,14.789 19.613,14.752 19.454,14.646 19.348,14.487 19.311,14.3 19.348,14.113 19.454,13.954 19.613,13.848 19.8,13.811 19.987,13.848 20.146,13.954 20.252,14.113 20.289,14.3
  pour cut-out: 19.339,25.25 19.302,25.437 19.196,25.596 19.037,25.702 18.85,25.739 18.663,25.702 18.504,25.596 18.398,25.437 18.361,25.25 18.398,25.063 18.504,24.904 18.663,24.798 18.85,24.761 19.037,24.798 19.196,24.904 19.302,25.063 19.339,25.25
  pour cut-out: 19.216,11.6 19.18,11.778 19.079,11.929 18.928,12.03 18.75,12.066 18.572,12.03 18.421,11.929 18.32,11.778 18.284,11.6 18.32,11.422 18.421,11.271 18.572,11.17 18.75,11.134 18.928,11.17 19.079,11.271 19.18,11.422 19.216,11.6
  pour cut-out: 18.289,20.75 18.252,20.937 18.146,21.096 17.987,21.202 17.8,21.239 17.613,21.202 17.454,21.096 17.348,20.937 17.311,20.75 17.348,20.563 17.454,20.404 17.613,20.298 17.8,20.261 17.987,20.298 18.146,20.404 18.252,20.563 18.289,20.75
  pour cut-out: 18.139,16 18.102,16.187 17.996,16.346 17.837,16.452 17.65,16.489 17.463,16.452 17.304,16.346 17.198,16.187 17.161,16 17.198,15.813 17.304,15.654 17.463,15.548 17.65,15.511 17.837,15.548 17.996,15.654 18.102,15.813 18.139,16
  pour cut-out: 16.039,20.55 16.002,20.737 15.896,20.896 15.737,21.002 15.55,21.039 15.363,21.002 15.204,20.896 15.098,20.737 15.061,20.55 15.098,20.363 15.204,20.204 15.363,20.098 15.55,20.061 15.737,20.098 15.896,20.204 16.002,20.363 16.039,20.55
  pour cut-out: 15.439,23.2 15.402,23.387 15.296,23.546 15.137,23.652 14.95,23.689 14.763,23.652 14.604,23.546 14.498,23.387 14.461,23.2 14.498,23.013 14.604,22.854 14.763,22.748 14.95,22.711 15.137,22.748 15.296,22.854 15.402,23.013 15.439,23.2
  pour cut-out: 15.039,25.05 15.002,25.237 14.896,25.396 14.737,25.502 14.55,25.539 14.363,25.502 14.204,25.396 14.098,25.237 14.061,25.05 14.098,24.863 14.204,24.704 14.363,24.598 14.55,24.561 14.737,24.598 14.896,24.704 15.002,24.863 15.039,25.05
  pour cut-out: 10.989,6.65 10.952,6.837 10.846,6.996 10.687,7.102 10.5,7.139 10.313,7.102 10.154,6.996 10.048,6.837 10.011,6.65 10.048,6.463 10.154,6.304 10.313,6.198 10.5,6.161 10.687,6.198 10.846,6.304 10.952,6.463 10.989,6.65
  pour cut-out: 9.539,20.55 9.502,20.737 9.396,20.896 9.237,21.002 9.05,21.039 8.863,21.002 8.704,20.896 8.598,20.737 8.561,20.55 8.598,20.363 8.704,20.204 8.863,20.098 9.05,20.061 9.237,20.098 9.396,20.204 9.502,20.363 9.539,20.55
  pour cut-out: 9.911,14.581 9.874,14.768 9.768,14.926 9.609,15.032 9.422,15.07 9.235,15.032 9.076,14.926 8.97,14.768 8.933,14.581 8.97,14.393 9.076,14.235 9.235,14.129 9.422,14.092 9.609,14.129 9.768,14.235 9.874,14.393 9.911,14.581
  pour cut-out: 9.698,35.815 9.667,36.05 9.576,36.269 9.432,36.457 9.244,36.601 9.025,36.692 8.79,36.723 8.555,36.692 8.336,36.601 8.148,36.457 8.004,36.269 7.913,36.05 7.882,35.815 7.913,35.58 8.004,35.361 8.148,35.173 8.336,35.029 8.555,34.938 8.79,34.907 9.025,34.938 9.244,35.029 9.432,35.173 9.576,35.361 9.667,35.58 9.698,35.815
  pour cut-out: 7.158,38.355 7.127,38.59 7.036,38.809 6.892,38.997 6.704,39.141 6.485,39.232 6.25,39.263 6.015,39.232 5.796,39.141 5.608,38.997 5.464,38.809 5.373,38.59 5.342,38.355 5.373,38.12 5.464,37.901 5.608,37.713 5.796,37.569 6.015,37.478 6.25,37.447 6.485,37.478 6.704,37.569 6.892,37.713 7.036,37.901 7.127,38.12 7.158,38.355
  pour cut-out: 5.966,26.85 5.942,26.971 5.874,27.074 5.771,27.142 5.65,27.166 5.529,27.142 5.426,27.074 5.358,26.971 5.334,26.85 5.358,26.729 5.426,26.626 5.529,26.558 5.65,26.534 5.771,26.558 5.874,26.626 5.942,26.729 5.966,26.85
  pour cut-out: 4.689,11.8 4.652,11.987 4.546,12.146 4.387,12.252 4.2,12.289 4.013,12.252 3.854,12.146 3.748,11.987 3.711,11.8 3.748,11.613 3.854,11.454 4.013,11.348 4.2,11.311 4.387,11.348 4.546,11.454 4.652,11.613 4.689,11.8
  pour cut-out: 4.544,35.815 4.516,36.031 4.433,36.232 4.3,36.405 4.127,36.538 3.926,36.621 3.71,36.649 3.494,36.621 3.293,36.538 3.12,36.405 2.987,36.232 2.904,36.031 2.876,35.815 2.904,35.599 2.987,35.398 3.12,35.225 3.293,35.092 3.494,35.009 3.71,34.981 3.926,35.009 4.127,35.092 4.3,35.225 4.433,35.398 4.516,35.599 4.544,35.815
  pour cut-out: 3.739,20.3 3.702,20.487 3.596,20.646 3.437,20.752 3.25,20.789 3.063,20.752 2.904,20.646 2.798,20.487 2.761,20.3 2.798,20.113 2.904,19.954 3.063,19.848 3.25,19.811 3.437,19.848 3.596,19.954 3.702,20.113 3.739,20.3
  pour cut-out: 1.339,20.6 1.302,20.787 1.196,20.946 1.037,21.052 0.85,21.089 0.663,21.052 0.504,20.946 0.398,20.787 0.361,20.6 0.398,20.413 0.504,20.254 0.663,20.148 0.85,20.111 1.037,20.148 1.196,20.254 1.302,20.413 1.339,20.6
  pour cut-out: 1.939,14.3 1.902,14.487 1.796,14.646 1.637,14.752 1.45,14.789 1.263,14.752 1.104,14.646 0.998,14.487 0.961,14.3 0.998,14.113 1.104,13.954 1.263,13.848 1.45,13.811 1.637,13.848 1.796,13.954 1.902,14.113 1.939,14.3
  pour cut-out: 3.089,14.501 3.052,14.688 2.946,14.846 2.787,14.952 2.6,14.99 2.413,14.952 2.254,14.846 2.148,14.688 2.111,14.501 2.148,14.313 2.254,14.155 2.413,14.049 2.6,14.012 2.787,14.049 2.946,14.155 3.052,14.313 3.089,14.501
  text "3" at 0.575,36.5 h1.3 r270
Signal Layer 3:
  pour cut-out: 29.33,11.205 29.293,11.393 29.187,11.551 29.028,11.657 28.841,11.694 28.654,11.657 28.495,11.551 28.389,11.393 28.352,11.205 28.389,11.018 28.495,10.86 28.654,10.754 28.841,10.717 29.028,10.754 29.187,10.86 29.293,11.018 29.33,11.205
  pour cut-out: 28.939,8.75 28.902,8.937 28.796,9.096 28.637,9.202 28.45,9.239 28.263,9.202 28.104,9.096 27.998,8.937 27.961,8.75 27.998,8.563 28.104,8.404 28.263,8.298 28.45,8.261 28.637,8.298 28.796,8.404 28.902,8.563 28.939,8.75
  pour cut-out: 29.789,5.55 29.752,5.737 29.646,5.896 29.487,6.002 29.3,6.039 29.113,6.002 28.954,5.896 28.848,5.737 28.811,5.55 28.848,5.363 28.954,5.204 29.113,5.098 29.3,5.061 29.487,5.098 29.646,5.204 29.752,5.363 29.789,5.55
  pour cut-out: 27.016,11.3 26.98,11.478 26.879,11.629 26.728,11.73 26.55,11.766 26.372,11.73 26.221,11.629 26.12,11.478 26.084,11.3 26.12,11.122 26.221,10.971 26.372,10.87 26.55,10.834 26.728,10.87 26.879,10.971 26.98,11.122 27.016,11.3
  pour cut-out: 24.839,2.016 24.802,2.204 24.696,2.362 24.537,2.468 24.35,2.505 24.163,2.468 24.004,2.362 23.898,2.204 23.861,2.016 23.898,1.829 24.004,1.671 24.163,1.565 24.35,1.527 24.537,1.565 24.696,1.671 24.802,1.829 24.839,2.016
  pour cut-out: 17.589,1.25 17.552,1.437 17.446,1.596 17.287,1.702 17.1,1.739 16.913,1.702 16.754,1.596 16.648,1.437 16.611,1.25 16.648,1.063 16.754,0.904 16.913,0.798 17.1,0.761 17.287,0.798 17.446,0.904 17.552,1.063 17.589,1.25
  pour cut-out: 15.789,9.35 15.752,9.537 15.646,9.696 15.487,9.802 15.3,9.839 15.113,9.802 14.954,9.696 14.848,9.537 14.811,9.35 14.848,9.163 14.954,9.004 15.113,8.898 15.3,8.861 15.487,8.898 15.646,9.004 15.752,9.163 15.789,9.35
  pour cut-out: 26.299,3.74 26.262,3.927 26.156,4.086 25.997,4.192 25.81,4.229 25.623,4.192 25.464,4.086 25.358,3.927 25.321,3.74 25.358,3.553 25.464,3.394 25.623,3.288 25.81,3.251 25.997,3.288 26.156,3.394 26.262,3.553 26.299,3.74
  pour cut-out: 1.339,20.6 1.302,20.787 1.196,20.946 1.037,21.052 0.85,21.089 0.663,21.052 0.504,20.946 0.398,20.787 0.361,20.6 0.398,20.413 0.504,20.254 0.663,20.148 0.85,20.111 1.037,20.148 1.196,20.254 1.302,20.413 1.339,20.6
  pour cut-out: 3.739,20.3 3.702,20.487 3.596,20.646 3.437,20.752 3.25,20.789 3.063,20.752 2.904,20.646 2.798,20.487 2.761,20.3 2.798,20.113 2.904,19.954 3.063,19.848 3.25,19.811 3.437,19.848 3.596,19.954 3.702,20.113 3.739,20.3
  pour cut-out: 4.544,35.815 4.516,36.031 4.433,36.232 4.3,36.405 4.127,36.538 3.926,36.621 3.71,36.649 3.494,36.621 3.293,36.538 3.12,36.405 2.987,36.232 2.904,36.031 2.876,35.815 2.904,35.599 2.987,35.398 3.12,35.225 3.293,35.092 3.494,35.009 3.71,34.981 3.926,35.009 4.127,35.092 4.3,35.225 4.433,35.398 4.516,35.599 4.544,35.815
  pour cut-out: 4.689,11.8 4.652,11.987 4.546,12.146 4.387,12.252 4.2,12.289 4.013,12.252 3.854,12.146 3.748,11.987 3.711,11.8 3.748,11.613 3.854,11.454 4.013,11.348 4.2,11.311 4.387,11.348 4.546,11.454 4.652,11.613 4.689,11.8
  pour cut-out: 9.698,35.815 9.667,36.05 9.576,36.269 9.432,36.457 9.244,36.601 9.025,36.692 8.79,36.723 8.555,36.692 8.336,36.601 8.148,36.457 8.004,36.269 7.913,36.05 7.882,35.815 7.913,35.58 8.004,35.361 8.148,35.173 8.336,35.029 8.555,34.938 8.79,34.907 9.025,34.938 9.244,35.029 9.432,35.173 9.576,35.361 9.667,35.58 9.698,35.815
  pour cut-out: 9.911,14.581 9.874,14.768 9.768,14.926 9.609,15.032 9.422,15.07 9.235,15.032 9.076,14.926 8.97,14.768 8.933,14.581 8.97,14.393 9.076,14.235 9.235,14.129 9.422,14.092 9.609,14.129 9.768,14.235 9.874,14.393 9.911,14.581
  pour cut-out: 10.989,6.65 10.952,6.837 10.846,6.996 10.687,7.102 10.5,7.139 10.313,7.102 10.154,6.996 10.048,6.837 10.011,6.65 10.048,6.463 10.154,6.304 10.313,6.198 10.5,6.161 10.687,6.198 10.846,6.304 10.952,6.463 10.989,6.65
  text "4" at 0.575,35.625 h1.3 r270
